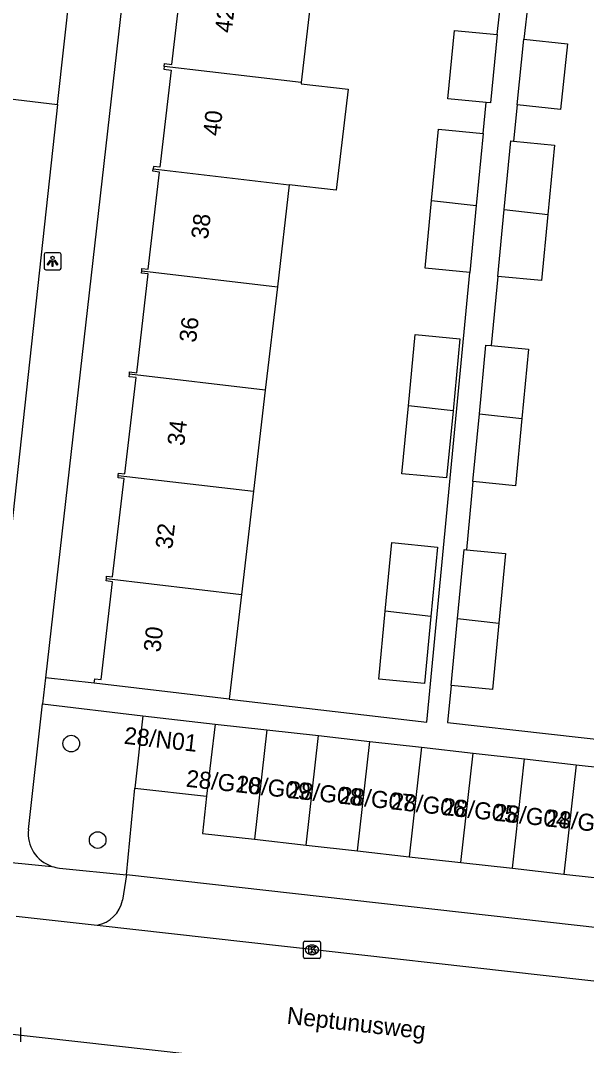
# Model space of a CAD drawing. Extents: x 161928 to 163055, y 386475 to 387428.
# Drawn here: x 162265.7 to 162299, y 386563.5 to 386623.6 of the extents above; entities that cross this region are included whole.
import ezdxf

# ---------------------------------------------------------------- set-up
doc = ezdxf.new("R2010")
doc.units = 0
for name, color, linetype in [('IMGEO_Boom', 7, 'Continuous'), ('IMGEO_Kolk', 7, 'Continuous'), ('IMGEO_Lichtpunt', 7, 'Continuous'), ('IMGEO_Openbare_ruimte_label', 7, 'Continuous'), ('IMGEO_Pand', 7, 'Continuous'), ('IMGEO_Pand_nummerreeks', 7, 'Continuous'), ('IMGEO_Parkeervlak_open', 7, 'Continuous'), ('IMGEO_Rijbaan_lokaal_open', 7, 'Continuous'), ('IMGEO_Voetpad_open', 7, 'Continuous')]:
    doc.layers.add(name, color=color, linetype=linetype)

msp = doc.modelspace()

# ---------------------------------------------------------------- linework, layer by layer
at = {"layer": 'IMGEO_Boom'}
for centre in [(162268.731, 386581.173), (162270.278, 386575.515)]:
    msp.add_circle(centre, 0.489, dxfattribs=at)
at = {"layer": 'IMGEO_Kolk'}
for p, q in [((162282.362, 386568.646), (162282.362, 386569.498)), ((162282.437, 386569.572), (162283.289, 386569.572)), ((162283.363, 386569.498), (162283.363, 386568.646)), ((162282.85, 386569.352), (162282.875, 386569.352)), ((162283.289, 386568.572), (162282.437, 386568.572)), ((162282.873, 386568.792), (162282.848, 386568.792)), ((162265.746, 386564.518), (162265.746, 386563.666))]:
    msp.add_line(p, q, dxfattribs=at)
for points in [[(162282.362, 386568.646), (162282.362, 386569.498)], [(162282.437, 386569.572), (162283.289, 386569.572)], [(162283.363, 386569.498), (162283.363, 386568.646)], [(162282.683, 386569.272), (162282.806, 386569.272), (162282.806, 386569.121), (162282.936, 386569.272), (162283.1, 386569.272), (162282.954, 386569.121), (162283.107, 386568.872), (162282.955, 386568.872), (162282.87, 386569.036), (162282.806, 386568.969), (162282.806, 386568.872), (162282.683, 386568.872), (162282.683, 386569.272)], [(162283.289, 386568.572), (162282.437, 386568.572)], [(162265.746, 386564.518), (162265.746, 386563.666)]]:
    msp.add_lwpolyline(points, dxfattribs=at)
for centre, start, end in [((162282.439, 386569.496), 91.55205, 178.44795), ((162282.439, 386569.496), 91.55205, 178.44795), ((162283.287, 386569.496), 1.55205, 88.44795), ((162283.287, 386569.496), 1.55205, 88.44795), ((162282.439, 386568.648), 181.55205, 268.44795), ((162282.439, 386568.648), 181.55205, 268.44795), ((162283.287, 386568.648), 271.55205, 358.44795), ((162283.287, 386568.648), 271.55205, 358.44795)]:
    msp.add_arc(centre, 0.0765, start, end, dxfattribs=at)
for centre, major_axis, ratio, start_param, end_param in [((162282.849, 386569.072), (-0.387, 0.002), 0.722429, 4.712389, 7.853982), ((162282.874, 386569.072), (-0.39, 0.002), 0.717154, 1.570796, 4.712389)]:
    msp.add_ellipse(centre, major_axis=major_axis, ratio=ratio, start_param=start_param, end_param=end_param, dxfattribs=at)
at = {"layer": 'IMGEO_Lichtpunt'}
for p, q in [((162267.131, 386609.885), (162267.131, 386609.078)), ((162267.131, 386609.885), (162267.131, 386609.078)), ((162268.033, 386609.98), (162267.225, 386609.98)), ((162268.033, 386609.98), (162267.225, 386609.98)), ((162268.127, 386609.078), (162268.127, 386609.885)), ((162268.127, 386609.078), (162268.127, 386609.885)), ((162267.225, 386608.984), (162268.033, 386608.984)), ((162267.225, 386608.984), (162268.033, 386608.984))]:
    msp.add_line(p, q, dxfattribs=at)
for points in [[(162267.505, 386609.549), (162267.544, 386609.521), (162267.356, 386609.259), (162267.318, 386609.286), (162267.505, 386609.549)], [(162267.607, 386609.501), (162267.654, 386609.501), (162267.654, 386609.179), (162267.607, 386609.179), (162267.607, 386609.501)], [(162267.717, 386609.521), (162267.755, 386609.548), (162267.942, 386609.286), (162267.903, 386609.258), (162267.717, 386609.521)]]:
    msp.add_lwpolyline(points, dxfattribs=at)
msp.add_circle((162267.63, 386609.683), 0.0994, dxfattribs=at)
for centre, start, end in [((162267.225, 386609.885), 90, 180), ((162267.225, 386609.885), 90, 180), ((162268.033, 386609.885), 0, 90), ((162268.033, 386609.885), 0, 90), ((162267.225, 386609.078), 180, 270), ((162267.225, 386609.078), 180, 270), ((162268.033, 386609.078), 270, 0), ((162268.033, 386609.078), 270, 360)]:
    msp.add_arc(centre, 0.0946, start, end, dxfattribs=at)
at = {"layer": 'IMGEO_Pand'}
for points in [[(162274.19, 386620.918), (162274.21, 386621.086), (162274.627, 386621.037), (162275.295, 386626.753), (162274.878, 386626.802), (162274.916, 386627.13)], [(162282.957, 386626.191), (162282.231, 386619.982)], [(162293.082, 386618.807), (162290.831, 386619.026), (162291.22, 386623.035), (162293.73, 386622.791)], [(162293.73, 386622.791), (162293.341, 386618.782), (162293.082, 386618.807)], [(162295.304, 386622.519), (162297.862, 386622.251), (162297.458, 386618.392), (162294.9, 386618.66)], [(162294.9, 386618.66), (162295.304, 386622.519)], [(162274.19, 386620.918), (162274.171, 386620.752), (162274.585, 386620.703), (162273.919, 386615), (162273.554, 386615.042), (162273.537, 386614.902)], [(162282.231, 386619.982), (162274.19, 386620.918)], [(162282.231, 386619.982), (162282.222, 386619.903), (162284.98, 386619.581), (162284.288, 386613.649), (162281.529, 386613.971)], [(162289.882, 386613.054), (162290.281, 386617.232), (162292.904, 386616.981)], [(162292.904, 386616.981), (162292.5, 386612.749)], [(162294.145, 386612.513), (162294.532, 386616.549), (162294.697, 386616.533)], [(162294.697, 386616.533), (162297.106, 386616.303), (162296.716, 386612.227)], [(162272.863, 386608.92), (162272.879, 386609.053), (162273.236, 386609.011), (162273.903, 386614.718), (162273.521, 386614.763), (162273.537, 386614.902)], [(162273.537, 386614.902), (162281.529, 386613.971)], [(162281.529, 386613.971), (162280.831, 386607.992)], [(162292.124, 386608.819), (162289.502, 386609.07), (162289.882, 386613.054)], [(162289.882, 386613.054), (162292.5, 386612.749)], [(162292.5, 386612.749), (162292.124, 386608.819)], [(162293.77, 386608.595), (162294.145, 386612.513)], [(162296.716, 386612.227), (162296.344, 386608.348), (162293.77, 386608.595)], [(162294.145, 386612.513), (162296.716, 386612.227)], [(162272.139, 386602.848), (162272.155, 386602.988), (162272.57, 386602.939), (162273.247, 386608.737), (162272.847, 386608.783), (162272.863, 386608.92)], [(162272.863, 386608.92), (162280.831, 386607.992)], [(162280.831, 386607.992), (162280.121, 386601.919)], [(162288.524, 386601.002), (162288.923, 386605.18), (162291.546, 386604.929), (162291.142, 386600.697)], [(162292.693, 386600.533), (162293.079, 386604.568), (162293.382, 386604.539)], [(162293.382, 386604.539), (162295.578, 386604.329), (162295.188, 386600.256)], [(162271.489, 386596.918), (162271.504, 386597.05), (162271.871, 386597.008), (162272.531, 386602.656), (162272.122, 386602.704), (162272.139, 386602.848)], [(162280.121, 386601.919), (162272.139, 386602.848)], [(162280.121, 386601.919), (162279.429, 386595.993)], [(162291.142, 386600.697), (162290.766, 386596.767), (162288.144, 386597.018), (162288.524, 386601.002)], [(162291.142, 386600.697), (162288.524, 386601.002)], [(162292.311, 386596.551), (162292.693, 386600.533)], [(162295.188, 386600.256), (162294.81, 386596.311), (162292.311, 386596.551)], [(162292.693, 386600.533), (162295.188, 386600.256)], [(162270.788, 386590.86), (162270.804, 386590.998), (162271.152, 386590.957), (162271.827, 386596.741), (162271.473, 386596.783), (162271.489, 386596.918)], [(162271.489, 386596.918), (162279.429, 386595.993)], [(162279.429, 386595.993), (162278.722, 386589.936)], [(162287.167, 386588.95), (162287.551, 386592.969), (162290.232, 386592.713), (162289.843, 386588.638)], [(162291.409, 386588.516), (162291.798, 386592.569), (162291.928, 386592.557)], [(162291.928, 386592.557), (162294.227, 386592.337), (162293.835, 386588.247)], [(162270.077, 386584.715), (162270.109, 386584.984), (162270.475, 386584.941), (162271.145, 386590.677), (162270.772, 386590.721), (162270.788, 386590.86)], [(162270.788, 386590.86), (162278.722, 386589.936)], [(162278.722, 386589.936), (162278.004, 386583.789)], [(162289.843, 386588.638), (162289.468, 386584.708), (162286.787, 386584.965), (162287.167, 386588.95)], [(162289.843, 386588.638), (162287.167, 386588.95)], [(162291.032, 386584.576), (162291.409, 386588.516)], [(162293.835, 386588.247), (162293.461, 386584.343), (162291.032, 386584.576)], [(162291.409, 386588.516), (162293.835, 386588.247)], [(162278.004, 386583.789), (162275.044, 386584.135), (162270.077, 386584.715)], [(162272.929, 386582.802), (162272.452, 386578.561)], [(162272.929, 386582.802), (162277.181, 386582.324)], [(162277.181, 386582.324), (162276.676, 386578.086)], [(162277.181, 386582.324), (162280.209, 386581.983)], [(162280.209, 386581.983), (162279.486, 386575.56)], [(162280.209, 386581.983), (162283.237, 386581.642)], [(162282.514, 386575.22), (162283.237, 386581.642)], [(162283.237, 386581.642), (162286.265, 386581.302)], [(162285.542, 386574.879), (162286.265, 386581.302)], [(162286.265, 386581.302), (162289.293, 386580.961)], [(162289.293, 386580.961), (162288.57, 386574.538)], [(162289.293, 386580.961), (162292.321, 386580.62)], [(162291.598, 386574.197), (162292.321, 386580.62)], [(162292.321, 386580.62), (162295.349, 386580.279)], [(162294.626, 386573.857), (162295.349, 386580.279)], [(162295.349, 386580.279), (162298.377, 386579.938)], [(162298.377, 386579.938), (162297.654, 386573.516)], [(162298.377, 386579.938), (162301.405, 386579.598)], [(162272.452, 386578.561), (162276.676, 386578.086)], [(162276.676, 386578.086), (162276.431, 386575.904), (162279.486, 386575.56)], [(162279.486, 386575.56), (162282.514, 386575.22)], [(162282.514, 386575.22), (162285.542, 386574.879)], [(162285.542, 386574.879), (162288.57, 386574.538)], [(162288.57, 386574.538), (162291.598, 386574.197)], [(162291.598, 386574.197), (162294.626, 386573.857)], [(162294.626, 386573.857), (162297.654, 386573.516)], [(162297.654, 386573.516), (162300.682, 386573.175)]]:
    msp.add_lwpolyline(points, dxfattribs=at)
at = {"layer": 'IMGEO_Parkeervlak_open'}
msp.add_lwpolyline([(162261.058, 386619.512), (162267.925, 386618.682)], dxfattribs=at)
at = {"layer": 'IMGEO_Rijbaan_lokaal_open'}
for points in [[(162265.483, 386571.051), (162270.245, 386570.518)], [(162270.245, 386570.518), (162307.612, 386566.339)], [(162315.022, 386558.52), (162264.757, 386564.157)]]:
    msp.add_lwpolyline(points, dxfattribs=at)
at = {"layer": 'IMGEO_Voetpad_open'}
for points in [[(162272.027, 386627.483), (162267.22, 386585.039)], [(162293.73, 386622.791), (162293.978, 386624.889), (162282.957, 386626.191)], [(162267.925, 386618.682), (162268.683, 386625.611)], [(162304.745, 386623.598), (162295.562, 386624.702), (162295.304, 386622.519)], [(162292.904, 386616.981), (162293.082, 386618.807)], [(162267.925, 386618.682), (162265.21, 386593.847)], [(162294.9, 386618.66), (162294.697, 386616.533)], [(162278.004, 386583.789), (162289.6, 386582.435), (162292.124, 386608.819)], [(162293.77, 386608.595), (162293.382, 386604.539)], [(162292.311, 386596.551), (162291.928, 386592.557)], [(162267.22, 386585.039), (162267.046, 386583.503)], [(162270.077, 386584.715), (162267.22, 386585.039)], [(162291.032, 386584.576), (162290.824, 386582.406), (162302.673, 386581.088)], [(162266.212, 386576.14), (162267.046, 386583.503)], [(162267.046, 386583.503), (162272.929, 386582.802)], [(162271.969, 386573.476), (162272.452, 386578.561)], [(162260.284, 386574.693), (162267.592, 386573.969)], [(162268.038, 386573.873), (162271.969, 386573.476)], [(162271.969, 386573.476), (162271.745, 386571.979)], [(162306.441, 386569.606), (162271.969, 386573.476)]]:
    msp.add_lwpolyline(points, dxfattribs=at)
for centre, radius, start, end in [((162268.243, 386575.907), 2.045, 173.46187, 251.42243), ((162268.257, 386575.972), 2.111, 251.64822, 264.05701), ((162269.9, 386572.373), 1.887, 280.5377, 347.95308)]:
    msp.add_arc(centre, radius, start, end, dxfattribs=at)

# ---------------------------------------------------------------- texts
at = {"layer": 'IMGEO_Openbare_ruimte_label'}
msp.add_text('Neptunusweg', height=1, rotation=353.57125, dxfattribs=at).set_placement((162281.35, 386564.737))
at = {"layer": 'IMGEO_Pand_nummerreeks'}
for s, rotation, p in [('42', 83.42409, (162278.147, 386622.853)), ('40', 83.42265, (162277.449, 386616.801)), ('38', 83.42409, (162276.751, 386610.742)), ('36', 83.42409, (162276.052, 386604.681)), ('34', 83.42409, (162275.354, 386598.622)), ('32', 83.42409, (162274.655, 386592.561)), ('30', 83.42409, (162273.957, 386586.508)), ('28/N01', 353.57125, (162271.789, 386581.17)), ('28/G10', 353.72465, (162275.431, 386578.65)), ('28/G09', 353.72465, (162278.366, 386578.328)), ('28/G08', 353.72465, (162281.403, 386577.994)), ('28/G07', 353.72465, (162284.431, 386577.661)), ('28/G06', 353.72465, (162287.462, 386577.327)), ('28/G05', 353.72465, (162290.494, 386576.994)), ('28/G04', 353.72465, (162293.525, 386576.661)), ('28/G03', 353.72465, (162296.556, 386576.327))]:
    msp.add_text(s, height=1, rotation=rotation, dxfattribs=at).set_placement(p)

doc.saveas('drawing.dxf')
